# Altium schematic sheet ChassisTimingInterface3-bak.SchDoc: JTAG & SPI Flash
size B; DocumentNumber: 4; Revision: C; SheetNumber: 4; SheetTotal: 12
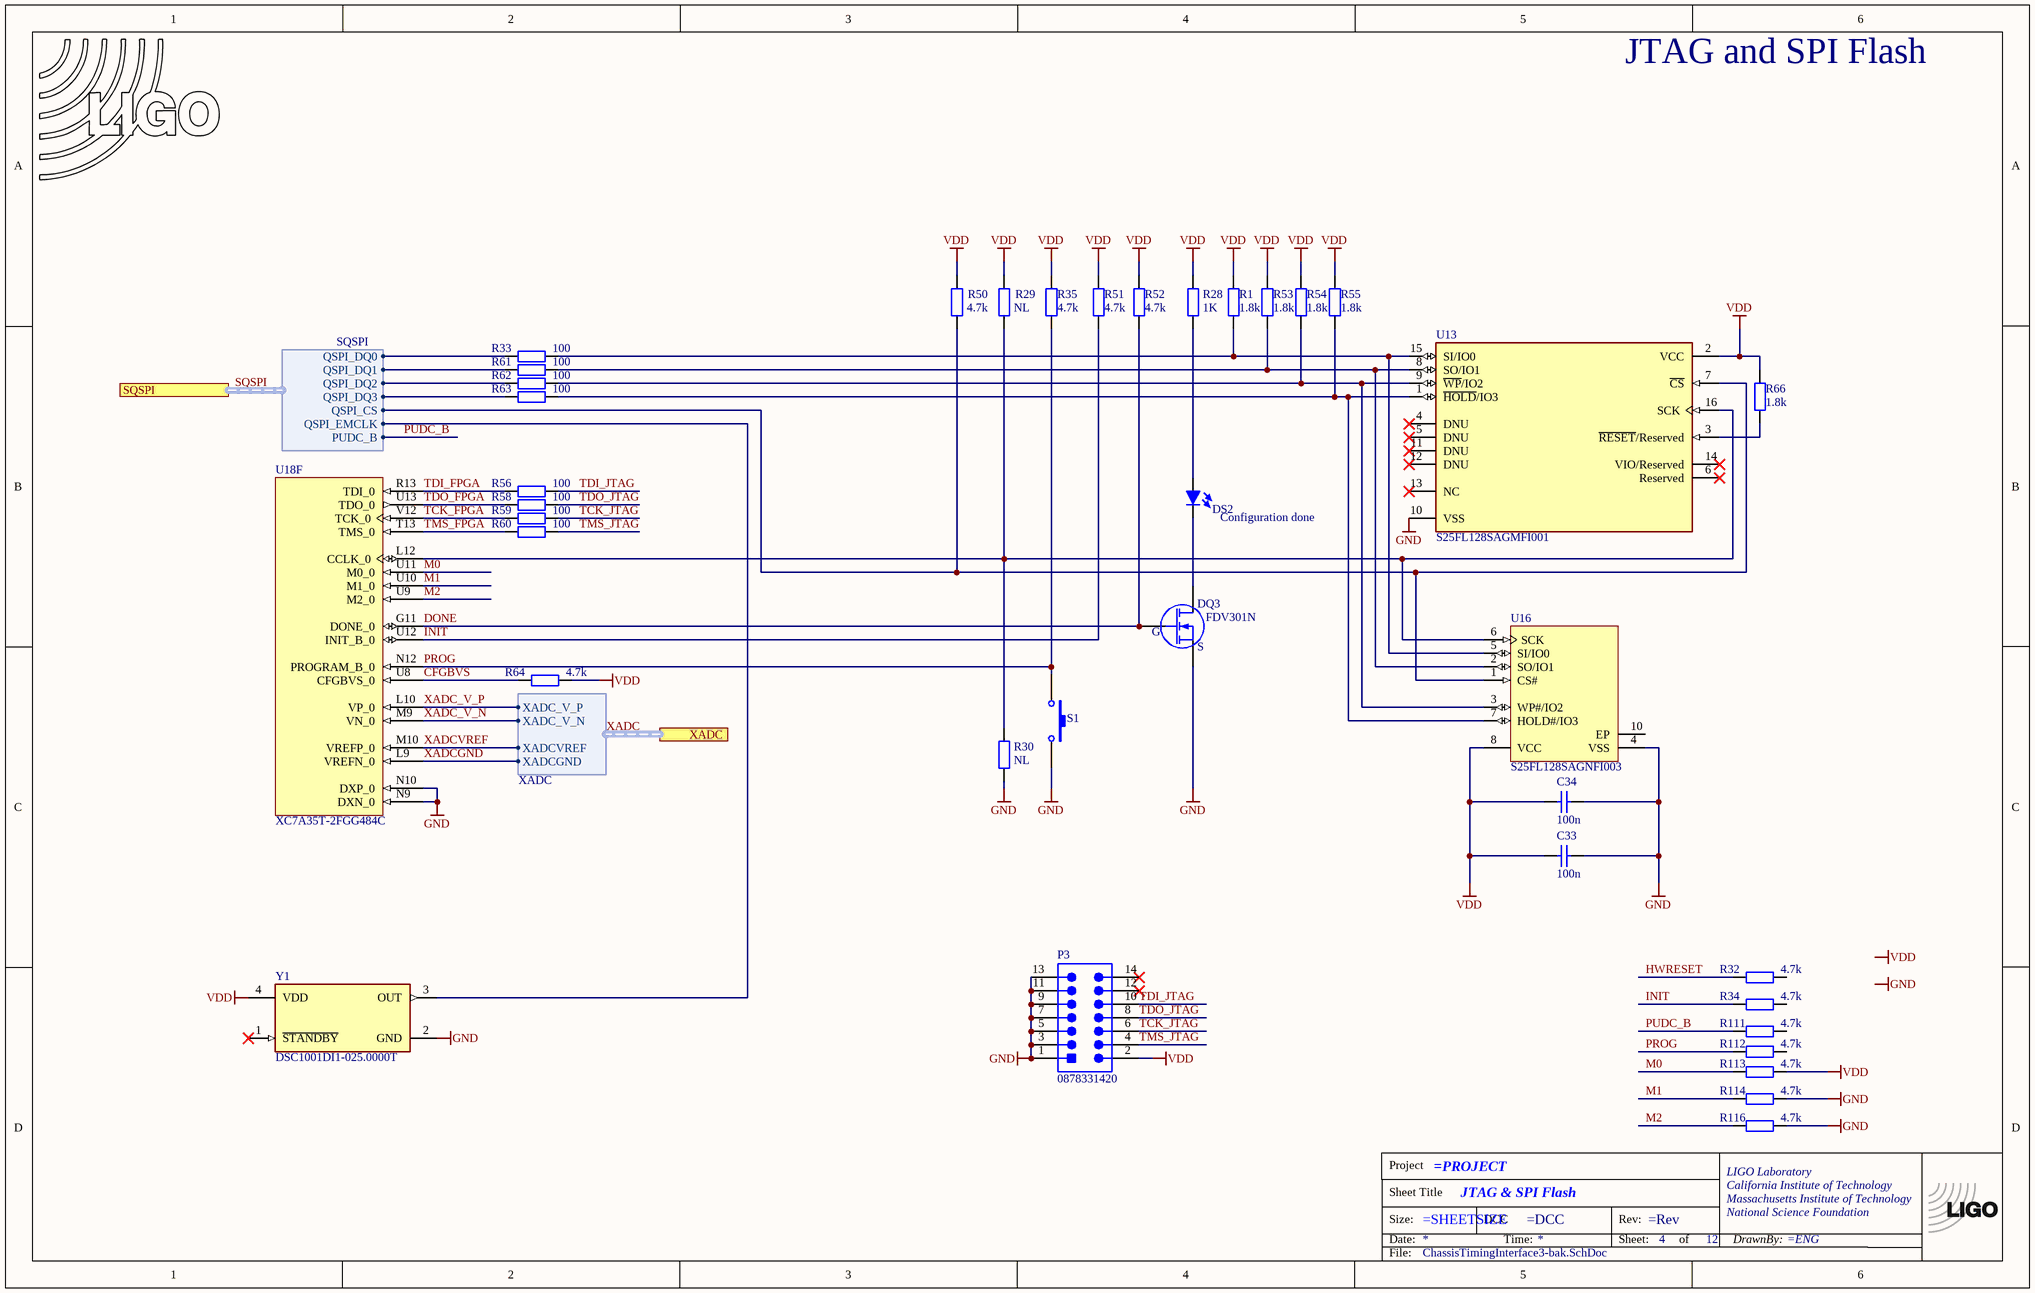
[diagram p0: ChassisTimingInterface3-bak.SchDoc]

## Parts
*?  TitleBlock  (value not drawn)  (graphical)
C33  100n  [CC1005-0402]
C34  100n  [CC1005-0402]
DS2  LED  [LED-0805]  (value not drawn)
LOGO3  LIGO logo  [LIGO_LOGO]  (value not drawn)  (graphical)
P3  0878331420  [2MM_HDR2X7_RA]
Q3  FDV301N  [SO-G3/C2.25]
R1  1.8k  [CR1005-0402]
R28  1K  [CR1005-0402]
R29  NL  [CR1005-0402]
R30  NL  [CR1005-0402]
R32  4.7k  [CR1005-0402]
R33  100  [CR1005-0402]
R34  4.7k  [CR1005-0402]
R35  4.7k  [CR1005-0402]
R50  4.7k  [CR1005-0402]
R51  4.7k  [CR1005-0402]
R52  4.7k  [CR1005-0402]
R53  1.8k  [CR1005-0402]
R54  1.8k  [CR1005-0402]
R55  1.8k  [CR1005-0402]
R56  100  [CR1005-0402]
R58  100  [CR1005-0402]
R59  100  [CR1005-0402]
R60  100  [CR1005-0402]
R61  100  [CR1005-0402]
R62  100  [CR1005-0402]
R63  100  [CR1005-0402]
R64  4.7k  [CR1005-0402]
R66  1.8k  [CR1005-0402]
R111  4.7k  [CR1005-0402]
R112  4.7k  [CR1005-0402]
R113  4.7k  [CR1005-0402]
R114  4.7k  [CR1005-0402]
R116  4.7k  [CR1005-0402]
S1  B3SN-3112P  [SW_SMD_6MM]  (value not drawn)
U13  S25FL128SAGMFI001  [FP-002-15547-MFG]
U16  S25FL128SAGNFI003  [SPSN-WSON-8_L]
U18  XC7A35T-2FGG484C  [FGG484]  (part F of 12)
Y1  DSC1001DI1-025.0000T  [FP-CDFN2520-4LD-PL-1-MFG]

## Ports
SQSPI (harness SQSPI), XADC (harness XADC)

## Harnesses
SQSPI: QSPI_DQ0, QSPI_DQ1, QSPI_DQ2, QSPI_DQ3, QSPI_CS, QSPI_EMCLK, PUDC_B
XADC: XADCGND, XADCVREF, XADC_V_N, XADC_V_P

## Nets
GND: C33.1 C34.1 P3.1 P3.3 P3.5 P3.7 P3.9 P3.11 P3.13 Q3.2(S) R30.2 R114.2 R116.2 S1.3 S1.5 U13.10(VSS) U16.4(VSS) U18.N9(DXN_0) U18.N10(DXP_0) Y1.2(GND)
VDD: C33.2 C34.2 P3.2 R1.2 R28.1 R29.1 R35.2 R50.1 R51.2 R52.2 R53.2 R54.2 R55.2 R64.2 R66.2 R113.2 U13.2(VCC) U16.8(VCC) Y1.4(VDD)
CFGBVS: R64.1 U18.U8(CFGBVS_0)
DONE: Q3.1(G) R52.1 U18.G11(DONE_0)
HWRESET: R32.1
INIT: R34.1 R51.1 U18.U12(INIT_B_0)
M0: R113.1 U18.U11(M0_0)
M1: R114.1 U18.U10(M1_0)
M2: R116.1 U18.U9(M2_0)
PROG: R35.1 R112.1 S1.1 U18.N12(PROGRAM_B_0)
PUDC_B: R111.1 ; port SQSPI.PUDC_B
SQSPI.QSPI_CS: R50.2 U13.7(~{CS}) U16.1(CS#) ; port SQSPI.QSPI_CS
SQSPI.QSPI_DQ0: R33.2 ; port SQSPI.QSPI_DQ0
SQSPI.QSPI_DQ1: R61.2 ; port SQSPI.QSPI_DQ1
SQSPI.QSPI_DQ2: R62.2 ; port SQSPI.QSPI_DQ2
SQSPI.QSPI_DQ3: R63.2 ; port SQSPI.QSPI_DQ3
SQSPI.QSPI_EMCLK: Y1.3(OUT) ; port SQSPI.QSPI_EMCLK
TCK_FPGA: R59.2 U18.V12(TCK_0)
TCK_JTAG: P3.6 R59.1
TDI_FPGA: R56.2 U18.R13(TDI_0)
TDI_JTAG: P3.10 R56.1
TDO_FPGA: R58.2 U18.U13(TDO_0)
TDO_JTAG: P3.8 R58.1
TMS_FPGA: R60.2 U18.T13(TMS_0)
TMS_JTAG: P3.4 R60.1
XADC_V_N: U18.M9(VN_0) ; port XADC.XADC_V_N  [project net XADC.XADC_V_N]
XADC_V_P: U18.L10(VP_0) ; port XADC.XADC_V_P  [project net XADC.XADC_V_P]
XADCGND: U18.L9(VREFN_0) ; port XADC.XADCGND  [project net XADC.XADCGND]
XADCVREF: U18.M10(VREFP_0) ; port XADC.XADCVREF  [project net XADC.XADCVREF]
NetDS2_1: DS2.1(K) Q3.3(D)
NetDS2_2: DS2.2(A) R28.2
NetR1_1: R1.1 R33.1 U13.15(SI/IO0) U16.5(SI/IO0)
NetR29_2: R29.2 R30.1 U13.16(SCK) U16.6(SCK) U18.L12(CCLK_0)
NetR53_1: R53.1 R61.1 U13.8(SO/IO1) U16.2(SO/IO1)
NetR54_1: R54.1 R62.1 U13.9(~{WP}/IO2) U16.3(WP#/IO2)
NetR55_1: R55.1 R63.1 U13.1(~{HOLD}/IO3) U16.7(HOLD#/IO3)
NetR66_1: R66.1 U13.3(~{RESET}/Reserved)

Not connected (* = marked no-connect by the designer): P3 12* 14*; R32 2; R34 2; R111 2; R112 2; U13 4(DNU)* 5(DNU)* 6(Reserved)* 11(DNU)* 12(DNU)* 13(NC)* 14(VIO/Reserved)*; U16 10(EP); Y1 1(~{STANDBY})*

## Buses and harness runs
harness SQSPI = port SQSPI
harness XADC = port XADC

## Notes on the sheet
- JTAG and SPI Flash
- (near DS2) Configuration done
- Labels drawn without touching a wire or pin: GND, VDD

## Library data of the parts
C33 C34 = ChipCap: Capacitor, surface mount; Tolerance: 10%
DS2 = LED: Panel mount LED
LOGO3 = LIGO_logo
P3 = CN-2P-M-R14: 14 pin 2mm 7x2 header
Q3 = FDV301N: FDV301N, Digital FET, N-channel, SOT23; Part Number: FDV301NCT-ND
R1 R28-R30 R32-R35 R50-R56 R58-R64 R66 R111-R114 R116 = ChipRes1: Resistor, surface mount; Tolerance: 1%
S1 = B3SN-3112P: Switch, SMD, 6mm; Part Number: SW262CT-ND
U13 = CMP-12948-000005-1: IC FLASH 128M SPI 133MHZ 16SOIC; Manufacturer: Cypress Semiconductor; Standoff Height: 0.1mm; Memory Type: FLASH,NOR; Memory Size: 128Mbits; Min Supply Voltage: 1.65V; Access Time: 8ns; Max Supply Voltage: 3.6V; Nominal Supply Current: 16-100mA
U16 = CMP-1329-00027-1: MirrorBit Flash Non-Volatile Memory CMOS 3.0 Volt Core with Versatile I/O, Serial Peripheral Interface with Multi-I/O, 128 Mbit, 133 MHz, -40 to 85 degC, 8-Pin WSON (WNG008), RoHS, Tape and Reel; Manufacturer: Spansion; Speed: 133 MHz; VCC: 2.7 to 3.6 V; OTP: 1024 B
U18 = CMP-0383-00019-1: Artix-7 FPGA, 250 User I/Os, 4 GTP, 484-Ball BGA, Speed Grade 2, Commercial Grade, Pb-Free; Manufacturer: Xilinx; Total Block RAM: 1800 Kb; GTP: 4; Available User I/O: 250; Speed Grades: 2; Logic Cells: 33280; CMTs: 5
Y1 = CMP-06255-000005-1: MEMS OSC XO 25.0000MHZ CMOS SMD; Manufacturer: Microchip Technology; Automotive Grade: Grade 3; Max Junction Temp: +150°C; Stability: 50ppm; Min Supply Voltage: 1.7V; Max Supply Voltage: 3.6V; Frequency: 25MHz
